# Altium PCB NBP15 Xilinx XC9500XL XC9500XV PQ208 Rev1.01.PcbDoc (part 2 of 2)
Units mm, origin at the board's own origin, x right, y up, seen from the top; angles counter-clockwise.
Board outline 69 x 80.99 mm, 2 copper layers (Top Layer, Bottom Layer); 37 components, 186 nets, 485 pads, 89 vias.
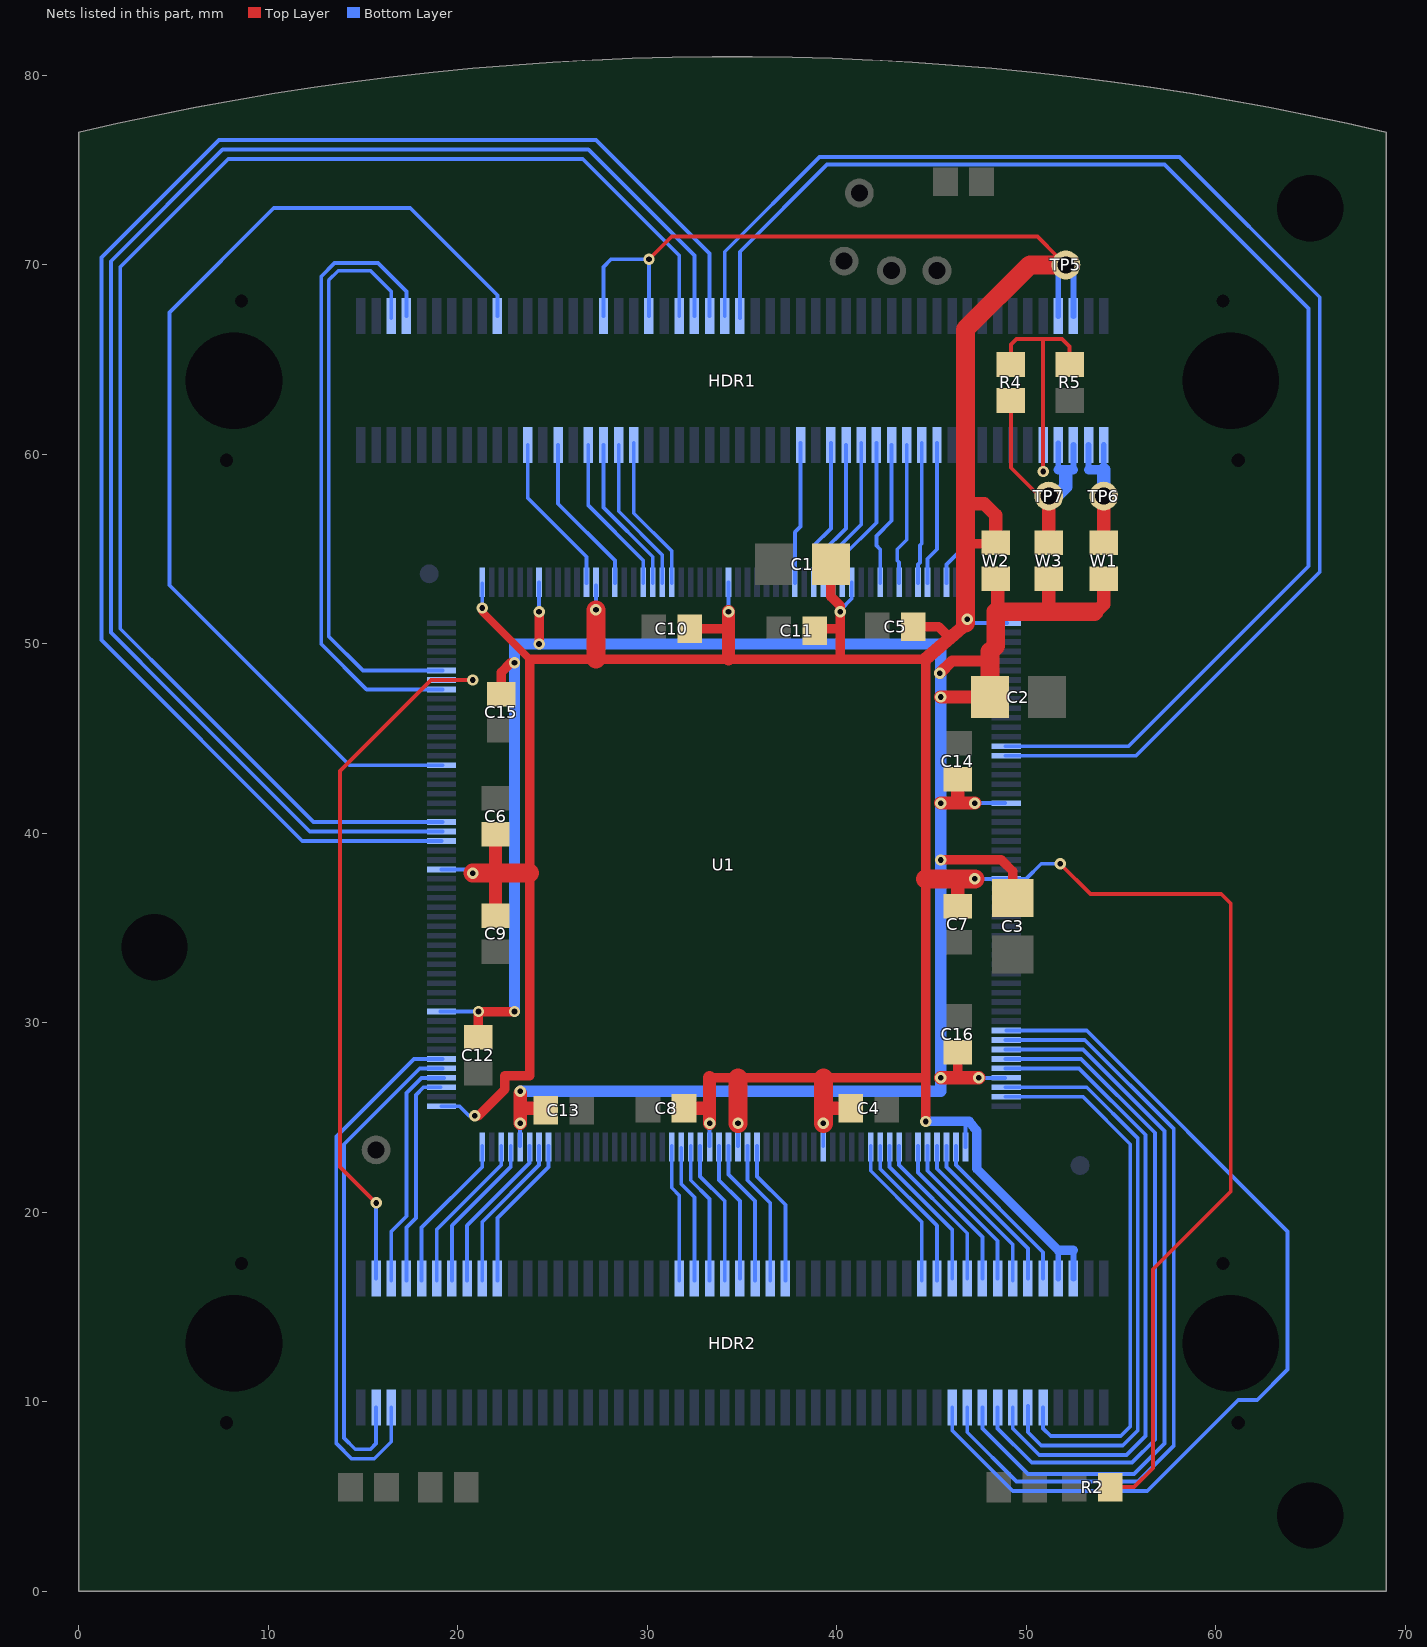
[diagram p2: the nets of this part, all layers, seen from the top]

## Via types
v1: diameter 0.6, hole 0.3, Top Layer to Bottom Layer, tented both sides, 86 vias
v2: diameter 0.9, hole 0.5, Top Layer to Bottom Layer, tented both sides, 3 vias

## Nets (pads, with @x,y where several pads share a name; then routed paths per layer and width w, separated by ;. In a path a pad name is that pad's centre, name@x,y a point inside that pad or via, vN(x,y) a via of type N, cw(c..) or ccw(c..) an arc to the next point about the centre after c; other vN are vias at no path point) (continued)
RAM_ADDR3: HDR1.33 U1.71 | length 8.4
  Bottom Layer w0.2: HDR1.33@27.7,60.5 27.7,57.2 30.3,54.6 U1.71@30.3,53.2
RAM_ADDR4: HDR1.65 U1.89 | length 7.8
  Bottom Layer w0.2: U1.89@39.3,53.2 39.3,54.9 40.5,56.1 HDR1.65@40.5,60.5
RAM_ADDR5: HDR1.69 U1.91 | length 8.1
  Bottom Layer w0.2: U1.91@40.3,53.2 40.3,54.6 42.1,56.4 HDR1.69@42.1,60.6
RAM_ADDR6: HDR1.73 U1.97 | length 7.5
  Bottom Layer w0.2: U1.97@43.3,53.2 43.3,54.3 43.2,54.4 43.2,55 43.7,55.5 HDR1.73@43.7,60.5
RAM_ADDR7: HDR1.77 U1.100 | length 7.6
  Bottom Layer w0.2: U1.100@44.8,53.2 44.8,54.5 45.3,55 HDR1.77@45.3,60.5 HDR1.77@45.3,60.6
RAM_ADDR8: HDR1.75 U1.99 | length 7.5
  Bottom Layer w0.2: U1.99@44.3,53.2 44.3,54.2 44.4,54.3 44.4,55.2 44.5,55.3 HDR1.75@44.5,60.6
RAM_ADDR9: HDR1.71 U1.95 | length 7.7
  Bottom Layer w0.2: U1.95@42.3,53.2 42.3,55 42.1,55.2 42.1,55.7 42.9,56.5 HDR1.71@42.9,60.5
RAM_ADDR10: HDR1.67 U1.90 | length 8
  Bottom Layer w0.2: U1.90@39.8,53.2 39.8,54.8 41.3,56.3 HDR1.67@41.3,60.6
RAM_ADDR11: HDR1.63 U1.88 | length 7.8
  Bottom Layer w0.2: U1.88@38.8,53.2 38.8,55.2 39.7,56.1 HDR1.63@39.7,60.6
RAM_ADDR12: HDR1.59 U1.86 | length 7.5
  Bottom Layer w0.2: U1.86@37.8,53.2 37.8,55.9 38.1,56.2 HDR1.59@38.1,60.5 HDR1.59@38.1,60.6
RAM_ADDR13: HDR1.35 U1.72 | length 8.3
  Bottom Layer w0.2: HDR1.35@28.5,60.5 28.5,57 30.8,54.7 U1.72@30.8,53.2
RAM_ADDR14: HDR1.31 U1.70 | length 8.5
  Bottom Layer w0.2: HDR1.31@26.9,60.5 26.9,57.3 29.8,54.4 U1.70@29.8,53.2
RAM_ADDR15: HDR1.27 U1.67 | length 8.5
  Bottom Layer w0.2: HDR1.27@25.3,60.5 25.3,57.4 28.3,54.4 U1.67@28.3,53.2
RAM_ADDR16: HDR1.23 U1.64 | length 8.6
  Bottom Layer w0.2: HDR1.23@23.7,60.5 23.7,57.7 26.8,54.6 U1.64@26.8,53.2
RAM_CS: HDR1.37 U1.73 | length 8.2
  Bottom Layer w0.2: HDR1.37@29.3,60.6 HDR1.37@29.3,60.5 29.3,56.9 31.3,54.9 U1.73@31.3,53.2
RED0: HDR1.6 U1.47 | length 30.9
  Bottom Layer w0.2: HDR1.6@16.5,67.2 16.5,68.6 15.4,69.7 13.7,69.7 13.2,69.2 13.2,51.2 13.2,50.4 15,48.6 U1.47@19.2,48.6
RED1: HDR1.8 U1.45 | length 33.5
  Bottom Layer w0.2: HDR1.8@17.3,67.3 17.3,68.6 15.8,70.1 13.5,70.1 12.8,69.4 12.8,50 15.2,47.6 U1.45@19.2,47.6
REF_CLK: HDR2.4 U1.46 | length 38.3
  Top Layer w0.2: v1(15.7,20.5) 13.8,22.4 13.8,43.3 18.6,48.1 v1(20.8,48.1)
  Bottom Layer w0.2: HDR2.4@15.7,16.5 v1(15.7,20.5) ; U1.46@19.1,48.1 v1(20.8,48.1)
SCL: HDR2.5 U1.6 | length 28.9
  Bottom Layer w0.2: HDR2.5@16.5,9.7 16.5,7.9 15.6,7 14.4,7 13.6,7.8 13.6,24 17.7,28.1 U1.6@19.2,28.1
SDA: HDR2.3 U1.5 | length 26.3
  Bottom Layer w0.2: HDR2.3@15.7,9.7 15.7,7.8 15.4,7.5 14.6,7.5 14,8.1 14,23.6 18,27.6 U1.5@19.2,27.6
SP0: HDR2.79 U1.148 | length 49.4
  Bottom Layer w0.2: HDR2.79@46.1,9.7 46.1,8.5 49.3,5.3 56.4,5.3 61.2,10.1 62.2,10.1 63.8,11.7 63.8,19 53.2,29.6 U1.148@48.95,29.6
SP1: HDR2.81 U1.149 | length 41.6
  Bottom Layer w0.2: HDR2.81@46.9,9.7 46.9,8.4 49.5,5.8 55.9,5.8 57.8,7.7 57.8,8 57.8,24.4 53.1,29.1 U1.149@48.9,29.1
SP2: HDR2.83 U1.150 | length 39
  Bottom Layer w0.2: HDR2.83@47.7,9.7 47.7,8.6 50.1,6.2 55.7,6.2 57.3,7.8 57.3,24.3 53,28.6 U1.150@48.9,28.6
SP3: HDR2.85 U1.151 | length 36.4
  Bottom Layer w0.2: HDR2.85@48.5,9.7 48.5,8.6 50.3,6.8 55.3,6.8 55.6,6.8 56.8,8 56.8,24.2 52.9,28.1 52.6,28.1 U1.151@48.9,28.1
SP4: HDR2.87 U1.152 | length 33.8
  Bottom Layer w0.2: U1.152@48.9,27.6 52.8,27.6 56.3,24.1 56.3,8.2 55.3,7.2 50.7,7.2 49.3,8.6 HDR2.87@49.3,9.7
SP5: HDR2.89 U1.154 | length 31.3
  Bottom Layer w0.2: U1.154@48.9,26.6 53.2,26.6 55.9,23.9 55.9,8.5 55.1,7.7 50.8,7.7 50.1,8.4 HDR2.89@50.1,9.8
SP6: HDR2.91 U1.155 | length 28.6
  Bottom Layer w0.2: U1.155@48.9,26.1 52.7,26.1 53,26.1 55.5,23.6 55.5,8.7 55,8.2 51.3,8.2 50.9,8.6 HDR2.91@50.9,9.7
SP7: HDR2.92 U1.158 | length 8.9
  Bottom Layer w0.2: U1.158@46.3,23.5 46.3,22.5 50.9,17.9 HDR2.92@50.9,16.5
SP8: HDR2.90 U1.159 | length 8.8
  Bottom Layer w0.2: U1.159@45.8,23.5 45.8,22.4 50.1,18.1 HDR2.90@50.1,16.5
SP9: HDR2.88 U1.160 | length 8.8
  Bottom Layer w0.2: U1.160@45.3,23.5 45.3,22.3 49.3,18.3 HDR2.88@49.3,16.5 HDR2.88@49.3,16.4
SP10: HDR2.86 U1.161 | length 8.5
  Bottom Layer w0.2: U1.161@44.8,23.5 44.8,22.2 48.5,18.5 HDR2.86@48.5,16.5
SP11: HDR2.84 U1.162 | length 8.4
  Bottom Layer w0.2: U1.162@44.3,23.5 44.3,22.1 47.7,18.7 HDR2.84@47.7,16.5
SP12: HDR2.82 U1.164 | length 8.5
  Bottom Layer w0.2: U1.164@43.3,23.5 43.3,22.5 46.9,18.9 HDR2.82@46.9,16.5
SP13: HDR2.80 U1.165 | length 8.4
  Bottom Layer w0.2: U1.165@42.8,23.5 42.8,22.4 46.1,19.1 HDR2.80@46.1,16.5
SP14: HDR2.78 U1.166 | length 8.3
  Bottom Layer w0.2: U1.166@42.3,23.5 42.3,22.3 45.3,19.3 HDR2.78@45.3,16.5 HDR2.78@45.3,16.4
SP15: HDR2.76 U1.167 | length 8.2
  Bottom Layer w0.2: U1.167@41.8,23.5 41.8,22.2 44.5,19.5 HDR2.76@44.5,16.4
SPI_CLK: HDR1.46 U1.30 | length 80.2
  Bottom Layer w0.2: U1.30@19.2,40.1 12.2,40.1 4.9,47.4 1.7,50.6 1.7,57.7 1.7,70.2 7.6,76.1 26.9,76.1 32.5,70.5 HDR1.46@32.5,67.3
SPI_DIN: HDR1.44 U1.31 | length 77.5
  Bottom Layer w0.2: U1.31@19.2,40.6 12.4,40.6 5.4,47.6 2.2,50.8 2.2,58.1 2.2,69.9 7.9,75.6 26.6,75.6 31.7,70.5 HDR1.44@31.7,67.3
SPI_DOUT: HDR1.50 U1.119 | length 75.1
  Bottom Layer w0.2: HDR1.50@34.1,67.3 34.1,70.7 39.1,75.7 58.1,75.7 65.5,68.3 65.5,59.7 65.5,53.8 55.8,44.1 U1.119@48.9,44.1
SPI_MODE: HDR1.52 U1.118 | length 72.1
  Bottom Layer w0.2: HDR1.52@34.9,67.2 34.9,70.5 34.9,70.7 39.5,75.3 57.3,75.3 64.9,67.7 64.9,54.1 55.4,44.6 U1.118@48.9,44.6
SPI_SEL: HDR1.48 U1.29 | length 83
  Bottom Layer w0.2: U1.29@19.15,39.6 11.8,39.6 1.2,50.2 1.2,70.4 7.4,76.6 27.3,76.6 33.3,70.6 HDR1.48@33.3,67.3
SW0: HDR2.44 U1.188 | length 7.3
  Bottom Layer w0.2: U1.188@31.3,23.5 31.3,21.3 31.7,20.9 HDR2.44@31.7,16.4
SW1: HDR2.46 U1.187 | length 7.3
  Bottom Layer w0.2: U1.187@31.8,23.4 31.8,21.5 32.5,20.8 HDR2.46@32.5,16.5 HDR2.46@32.5,16.4
SW2: HDR2.48 U1.186 | length 7.5
  Bottom Layer w0.2: U1.186@32.3,23.5 32.3,21.7 33.3,20.7 HDR2.48@33.3,16.5 HDR2.48@33.3,16.4
SW3: HDR2.50 U1.185 | length 7.6
  Bottom Layer w0.2: U1.185@32.8,23.5 32.8,21.9 34.1,20.6 HDR2.50@34.1,16.4
SW4: HDR2.52 U1.183 | length 7.5
  Bottom Layer w0.2: U1.183@33.8,23.5 33.8,21.7 34.9,20.6 HDR2.52@34.9,16.5
SW5: HDR2.54 U1.182 | length 7.7
  Bottom Layer w0.2: U1.182@34.3,23.5 34.3,22 35.7,20.6 HDR2.54@35.7,16.5 HDR2.54@35.7,16.4
SW6: HDR2.56 U1.180 | length 7.6
  Bottom Layer w0.2: U1.180@35.3,23.5 35.3,21.7 36.5,20.5 HDR2.56@36.5,16.5 HDR2.56@36.5,16.4
SW7: HDR2.58 U1.179 | length 7.7
  Bottom Layer w0.2: U1.179@35.8,23.5 35.8,21.9 37.3,20.4 HDR2.58@37.3,16.5 HDR2.58@37.3,16.4
SWC0: HDR2.18 U1.202 | length 8.3
  Bottom Layer w0.2: HDR2.18@21.3,16.4 21.3,19.5 24.3,22.5 U1.202@24.3,23.5
SWC1: HDR2.16 U1.203 | length 8.5
  Bottom Layer w0.2: HDR2.16@20.5,16.4 HDR2.16@20.5,16.5 20.5,19.3 23.8,22.6 U1.203@23.8,23.5
SWC2: HDR2.14 U1.205 | length 8.4
  Bottom Layer w0.2: HDR2.14@19.7,16.4 19.7,19.3 22.8,22.4 U1.205@22.8,23.5
SWC3: HDR2.6 U1.4 | length 12.6
  Bottom Layer w0.2: HDR2.6@16.5,16.4 16.5,19 17.3,19.8 17.3,26.3 18.1,27.1 U1.4@19.3,27.1
SWR0: HDR2.20 U1.201 | length 8.2
  Bottom Layer w0.2: HDR2.20@22.1,16.4 22.1,19.7 24.8,22.4 U1.201@24.8,23.5
SWR1: HDR2.12 U1.206 | length 8.5
  Bottom Layer w0.2: HDR2.12@18.9,16.4 18.9,19.1 22.3,22.5 U1.206@22.3,23.5
SWR2: HDR2.10 U1.208 | length 8.4
  Bottom Layer w0.2: HDR2.10@18.1,16.4 18.1,19.2 21.3,22.4 U1.208@21.3,23.5
SWR3: HDR2.8 U1.3 | length 11.5
  Bottom Layer w0.2: HDR2.8@17.3,16.4 HDR2.8@17.3,16.5 17.3,19.2 17.8,19.7 17.8,26.2 18.2,26.6 U1.3@19.1,26.6
TEST: HDR1.81 U1.102 | length 7.9
  Bottom Layer w0.2: U1.102@45.8,53.2 45.8,54.2 46.9,55.3 HDR1.81@46.9,60.5 HDR1.81@46.9,60.6
VCC: C1.1 C4.1 C5.1 C6.1 C7.1 C8.1 C9.1 C10.1 C11.1 HDR1.34 HDR1.40 HDR1.94 HDR1.96 HDR2.94 HDR2.96 R2.1 TP5.1 U1.1 U1.26 U1.53 U1.65 U1.79 U1.92 U1.105 U1.132 U1.157 U1.172 U1.181 U1.184 W2.1 | length 278.2
  Top Layer w0.2: v1@21.3,51.7 v1(21.3,51.9) ; v1(30.1,70.3) 31.3,71.5 31.8,71.5 ; 31.4,71.5 50.6,71.5 TP5.1@51.7,70.4 ; v1(51.8,38.4) 53.4,36.8 60.3,36.8 60.8,36.3 60.8,21.1 56.7,17 56.7,6.5 55.7,5.5 R2.1@54.4,5.5 ; R2.1@54.4,5.4 R2.1@54.45,5.4
  Top Layer w0.4: v1@21.3,51.7 23.8,49.2
  Top Layer w0.5: v1(20.9,25.1) 21.1,25.1 22.5,26.5 22.5,27.2 23.8,27.2 23.8,49.2 27.3,49.2 34.3,49.2 40.2,49.2 ; C10.1@32.3,50.8 34.3,50.8 ; 33.3,27.1 44.7,27.1 ; C11.1@38.85,50.8 40.2,50.8 ; C1.1@39.7,54.2 39.7,52.5 40.2,52 40.2,49.2 ; C5.1@44.1,50.9 45.4,50.9 45.988,50.312 ; v1(44.7,24.8) 44.7,27.1 ; 46.8,55.3 W2.1@48.4,55.3 ; 40.2,49.2 44.7,49.2 44.7,37.6 44.7,27.1
  Top Layer w0.7: C9.1@22,35.65 C6.1@22,39.95 ; C8.1@31.95,25.5 33.3,25.5 ; v1(33.3,24.7) 33.3,27.1 ; 34.3,49.2 v1(34.3,51.7) ; 39.3,25.5 C4.1@40.7,25.5 ; 44.7,49.2 45.988,50.312 ; 45.989,50.313 v1@46.843,51.05 ; C7.1@46.4,36.35 46.4,37.6 ; 46.9,65 46.9,57.4 47.8,57.4 48.4,56.8 W2.1@48.4,55.35
  Top Layer w1: v1(20.8,37.9) 23.8,37.9 ; 27.3,49.2 v1(27.3,51.8) ; v1(34.8,24.7) 34.8,27.1 ; v1(39.3,24.7) 39.3,27.1 ; 44.7,37.6 v1(47.3,37.6) ; v1@46.8,51.1 46.8,66.6 50.2,70 TP5.1@52.2,70
  Bottom Layer w0.2: U1.1@19.15,25.6 20.1,25.6 20.6,25.1 v1(20.9,25.1) ; U1.26@19.15,38.1 20.6,38.1 v1(20.8,37.9) ; v1(21.3,51.9) U1.53@21.3,53.2 ; v1(27.3,51.8) U1.65@27.3,53.1 ; HDR1.34@27.7,67.3 27.7,69.9 28.1,70.3 v1(30.1,70.3) HDR1.40@30.1,67.3 ; U1.184@33.3,23.5 v1(33.3,24.7) ; v1(34.3,51.7) U1.79@34.3,53.25 ; U1.181@34.8,23.5 v1(34.8,24.7) ; U1.172@39.3,23.5 v1(39.3,24.7) ; v1(40.2,51.7) 40.2,51.8 40.8,52.4 U1.92@40.8,53.25 ; U1.157@46.8,23.45 46.8,24.7 46.8,24.8 ; v1(46.9,51.3) 47.1,51.1 U1.105@49,51.1 ; v1(47.3,37.6) U1.132@48.95,37.6 ; U1.132@48.9,37.6 50,37.6 50.8,38.4 v1(51.8,38.4)
  Bottom Layer w0.3: HDR2.94@51.7,16.5 51.7,18 ; HDR1.94@51.7,67.3 TP5.1@51.7,70 ; HDR2.96@52.5,16.5 52.5,18 ; HDR1.96@52.5,67.3 TP5.1@52.5,70
  Bottom Layer w0.5: v1(44.7,24.8) 47,24.8 47.4,24.3 47.4,22.3 51.7,18 52.5,18
VCC2V5: HDR1.93 HDR1.95 R4.1 TP7.1 W3.1 | length 14.2
  Top Layer w0.2: R4.1@49.2,62.8 49.2,59.3 TP7.1@51.1,57.4
  Top Layer w0.7: W3.1@51.2,55.3 TP7.1@51.2,57.8
  Bottom Layer w0.3: 51.7,59.2 HDR1.93@51.7,60.6 ; 52.5,59.2 HDR1.95@52.5,60.5
  Bottom Layer w0.5: 51.7,59.2 52.5,59.2
  Bottom Layer w0.7: TP7.1@51.2,57.4 52.1,58.3 52.1,59
VCC5V: HDR1.97 HDR1.99 TP6.1 W1.1 | length 7.8
  Top Layer w0.7: W1.1@54.1,55.3 TP6.1@54.1,57.9
  Bottom Layer w0.3: 53.3,59.2 HDR1.97@53.3,60.5 ; 54.1,59.2 HDR1.99@54.1,60.5
  Bottom Layer w0.5: 53.3,59.2 54.1,59.2
  Bottom Layer w0.7: TP6.1@54.1,57.4 54.1,59.2
VCCINT: C2.1 C3.1 C12.1 C13.1 C14.1 C15.1 C16.1 U1.11 U1.59 U1.124 U1.153 U1.204 W1.2 W2.2 W3.2 | length 138.3
  Top Layer w0.5: C12.1@21.1,29.25 v1(21.1,30.6) v1(23,30.6) ; C15.1@22.3,47.35 22.3,48.5 22.8,49 v1(23,49) ; v1(24.3,50) v1(24.3,51.7) ; v1(45.5,38.6) 48.7,38.6 49.3,38 C3.1@49.3,36.6 ; 46.4,27.1 C16.1@46.4,28.45
  Top Layer w0.6: v1(45.45,48.45) 46.1,49.1 48.1,49.1
  Top Layer w0.7: v1(23.3,24.7) v1@23.3,26.3 ; 23.3,25.5 C13.1@24.9,25.5 ; v1(45.5,27.1) v1(47.5,27.1) ; v1(45.5,41.6) v1(47.3,41.6) ; v1(45.5,47.2) C2.1@48.1,47.2 ; 46.4,41.6 C14.1@46.4,42.85 ; 48.5,50.4 48.5,50.5 ; 48.5,51.7 W2.2@48.5,53.4 ; 51.2,51.7 W3.2@51.2,53.45 ; 53.6,51.6 54.1,52.1 W1.2@54.1,53.5
  Top Layer w1: C2.1@48.1,47.2 48.1,49.6 48.4,49.9 48.4,51.7 ; 48.6,51.7 53.6,51.7
  Bottom Layer w0.2: U1.11@19.1,30.6 U1.11@19.15,30.6 v1(21.1,30.6) ; U1.204@23.3,23.5 v1(23.3,24.7) ; v1(24.3,51.7) U1.59@24.3,53.25 ; v1(47.3,41.6) U1.124@48.9,41.6 ; v1(47.5,27.1) U1.153@48.9,27.1
  Bottom Layer w0.6: v1(23,30.6) 23,50 45.5,50 45.5,26.4 v1(23.3,26.4)
VDRIVE: HDR1.20 U1.37 | length 55.3
  Bottom Layer w0.2: U1.37@19.2,43.6 14.3,43.6 4.8,53.1 4.8,67.5 10.3,73 17.5,73 22.1,68.4 HDR1.20@22.1,67.3
VREF: HDR1.91 R4.2 R5.1 | length 14
  Top Layer w0.2: R4.2@49.2,64.7 49.2,65.8 49.5,66.1 51.9,66.1 52.3,65.7 R5.1@52.3,64.6 ; v1(50.9,59.1) 50.9,66.1
  Bottom Layer w0.2: v1(50.9,59.1) HDR1.91@50.9,60.5
pads on no net: HDR1.MH1 HDR1.MH2 HDR1.MH3 HDR1.MH4 HDR1.MH5 HDR1.MH6 HDR2.93 HDR2.95 HDR2.97 HDR2.99 HDR2.MH1 HDR2.MH2 HDR2.MH3 HDR2.MH4 HDR2.MH5 HDR2.MH6 U1.16 U1.25 U1.28

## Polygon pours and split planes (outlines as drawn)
GND on Top Layer "Top Layer-GND" (solid, remove dead copper, pour order 1000): 0.45,-0.295 69.45,-0.295 69.45,81.005 0.55,81.005 0.55,-0.195

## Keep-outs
Bottom Layer:
  circle w0.2: c18.5,53.7 r2
  circle w0.2: c52.85,22.475 r2
Keep-Out Layer:
  lines w1.8: 68.999,77 ccw(c34.5,-69.801) 0.001,77 0,0 69,0 ; 69.1,0 69.1,77

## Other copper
Top Layer:
  rectangle net VCC: 23.5,26.9 44.8,49.1
Bottom Layer:
  rectangle net VCC: 51.6,68.6 52.6,70.6
  rectangle net GND: 22,27.3 24.1,29.9
  rectangle net GND: 23.9,27.3 44.5,49.1

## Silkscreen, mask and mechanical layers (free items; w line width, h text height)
Top Overlay:
  lines w0.254: 38.4,68.1 40.4,70.1 ; 39.6,66.4 42.9,69.7 ; 39.9,75.1 41.2,73.8 ; 45.2,69.6 45.3,69.7 46.6,68.4 ; 51.2,57.6 54.1,60.5 ; 52.1,70 53.6,71.5 ; 54.1,57.7 55.2,58.8 ; 51.2,57.4 51.2,57.4
  text "(TDO)" at 36.2,74.8 h0.8
  text "(+3V3)" at 56.3,71 h0.8
  text "(TDI)" at 49.3,67.9 h0.8
  text "(TMS)" at 34.7,67.7 h0.8
  text "(TCK)" at 35.9,66 h0.8
  text "(+2V5)" at 54.4,59.7 h0.8
  text "(+5V)" at 57.9,58.4 h0.8
  text "(FPGA CLK)" at 19.8,22.8 h0.8
  text "LOADED" at 17.3,2.8 h0.8
  text "POWER" at 47.6,2.7 h0.8
Bottom Overlay:
  drawing of 849 lines, arcs and shapes, not listed
  text "REV 1.01" at 47.7,76.5 h1.3
  text "NBP15" at 54.9,76.5 h1.3
PCB Boundary:
  the board outline again, w0.25
  text "PCB boundary coincides with centre-line of tracks and arc" at 0,-12 h0.75
Gerber ID:
  text ".Layer_Name" at 0,-6 h0.75
Printout ID:
  text ".Printout_Name" at 0,-10 h0.75
Design Information:
  drawing of 719 lines, arcs and shapes, not listed
  text "NBP15 REV 1.01" at 317.627,202.041 h1.27
  text "DESIGN INFORMATION" at 261.62,201.914 h1.52
  text "BOARD NAME:" at 299.212,201.914 h1.52
  text "BOARD TECHNOLOGY" at 261.62,199.374 h1.52
  text "BOARD SIZE (REFER ALSO PROFILING INFORMATION)" at 309.88,199.374 h1.27
  text "69.00mm" at 312.6,197.1 h1.52
  text "11.811" at 277.419,197.012 h1.52
  text "81.00mm" at 335.6,197 h1.52
  text "7.874" at 291.389,196.885 h1.52
  text "7.874" at 264.446,196.834 h1.52
  text "X" at 328.549,196.326 h1.78
  text "(MIN. TRACK/   PADS  /   CLEARANCE     IN 0.001'')" at 260.096,194.294 h1.27
  text "MINIMUM ANNULAR RING 0.05MM (0.002'') EXTERNAL PER IPC-2221 CLASS 3 LEVEL C AND IS THE" at 261.62,191.754 h1.27
  text "MANUFACTURING REGISTRATION ALLOWANCE" at 261.62,189.468 h1.27
  text "LAND SIZE CALCULATION MINIMUM - NOMINAL HOLE SIZE + 0.508MM (0.020'')" at 261.62,186.674 h1.27
  text "AS INSTRUCTED" at 347.65,182.28 h1.52
  text "X" at 299.263,182.153 h1.52
  text "CIRCUIT TYPE:" at 261.62,182.102 h1.52
  text "SS" at 284.48,182.102 h1.27
  text "DS" at 302.26,182.102 h1.27
  text "X" at 316.865,182.102 h1.52
  text "PTH" at 320.04,182.102 h1.27
  text "ML" at 330.962,182.102 h1.27
  text "No. OFF" at 337.82,182.102 h1.27
  text "FINGER CONNECTOR DIM PER:" at 261.62,179.054 h1.52
  text "AS SHOWN" at 337.82,179.054 h1.27
  text "No. OFF TOTAL" at 278.384,176.26 h1.52
  text "ONE SIDE" at 320.04,176.26 h1.27
  text "BOTH SIDES" at 337.82,176.006 h1.27
  text "VIAS:" at 261.62,173.339 h1.52
  text "NONE" at 273.05,173.339 h1.14
  text "X" at 281.432,173.339 h1.52
  text "FEED THRU'" at 284.48,173.339 h1.14
  text "X" at 299.212,173.339 h1.52
  text "TENTED" at 302.26,173.339 h1.14
  text "BURIED LAYER SEQUENCE" at 320.04,173.339 h1.14
  text "UNIQUE DRILL" at 284.48,170.291 h1.14
  text "2 SIZE" at 302.26,170.291 h1.14
  text "BLIND LAYER SEQUENCE" at 320.04,170.291 h1.14
  text "Layer Stack Manager (Protel)" at 297.053,168.005 h1.27
  text "X" at 334.772,168.005 h1.52
  text "AS SHOWN" at 337.82,168.005 h1.27
  text "LAYER CONSTRUCTION PER:" at 261.62,167.878 h1.52
  text "Protel" at 342.646,165.338 h1.27
  text "(PFW)" at 352.933,165.211 h1.27
  text "ARTWORK:" at 261.62,165.084 h1.52
  text "MANUAL" at 284.48,165.084 h1.27
  text "DIGITISED" at 302.26,165.084 h1.27
  text "X" at 316.992,165.084 h1.52
  text "CAD" at 320.04,165.084 h1.27
  text "TYPE" at 330.962,165.084 h1.27
  text "ARTWORK/PATTERN MASTER LIST" at 261.62,160.385 h1.52
  text "DESCRIPTION" at 262.89,157.972 h1.27
  text "DRAWING No./CAD FILE REF." at 281.559,157.972 h1.27
  text "LAYER NAME" at 322.834,157.972 h1.27
  text "GERBER FILE REF" at 343.586,157.896 h1.27
  text "PCB FILE" at 261.366,155.432 h1.27
  text "BOC_XC95288_PQ208" at 281.237,155.356 h1.27
  text "PcbDoc" at 312.979,155.356 h1.02
  text "Top Paste Mask" at 321.158,152.892 h1.02
  text "GTP" at 363.779,152.816 h1.27
  text "GERBER FILE" at 261.366,152.765 h1.27
  text "GTO" at 363.728,150.327 h1.27
  text "Top Overlay" at 321.158,150.301 h1.02
  text "GERBER FILE" at 261.366,150.225 h1.27
  text "Top Solder Mask" at 321.158,147.863 h1.02
  text "GTS" at 363.779,147.736 h1.27
  text "GERBER FILE" at 261.366,147.685 h1.27
  text "TOP LAYER" at 321.158,145.272 h1.02
  text "GTL" at 363.779,145.196 h1.27
  text "GERBER FILE" at 261.366,145.145 h1.27
  text "BOTTOMLAYER" at 321.158,142.732 h1.02
  text "GBL" at 363.779,142.656 h1.27
  text "GERBER FILE" at 261.366,142.605 h1.27
  text "Bottom Solder Mask" at 321.158,140.243 h1.02
  text "GBS" at 363.779,140.116 h1.27
  text "GERBER FILE" at 261.366,140.065 h1.27
  text "Bottom Overlay" at 321.158,137.652 h1.02
  text "GBO" at 363.779,137.576 h1.27
  text "GERBER FILE" at 261.366,137.525 h1.27
  text "Bottom Paste Mask" at 321.158,135.163 h1.02
  text "GBP" at 363.779,135.036 h1.27
  text "GERBER FILE" at 261.366,134.985 h1.27
  text "PCB Boundary" at 321.158,132.572 h1.02
  text "GM1" at 363.779,132.496 h1.27
  text "GERBER FILE" at 261.366,132.445 h1.27
  text "APERTURE LIST" at 261.366,130.032 h1.27
  text "APR" at 313.979,129.956 h1.27
  text "DRILL REPORT" at 261.366,127.492 h1.27
  text "DRR" at 313.979,127.416 h1.27
  text "EXCELLON DRILL" at 261.366,124.952 h1.27
  text "TXT" at 313.979,124.876 h1.27
  text "MATERIAL:" at 261.62,99.298 h1.52
  text "GLASS FIBRE EPOXY RESIN NEMA GRADE FR4 (MIL-S-13949H)" at 287.274,99.044 h1.27
  text "X" at 284.607,98.917 h1.52
  text "THICKNESS:" at 269.494,96.123 h1.27
  text "0.8mm" at 287.274,96.123 h1.27
  text "1.2mm" at 304.927,96.123 h1.27
  text "1.6mm" at 322.58,96.123 h1.27
  text "2.4mm" at 340.36,96.123 h1.27
  text "3.2mm" at 358.14,96.123 h1.27
  text "X" at 320.167,95.996 h1.52
  text "TOLERANCE:" at 269.367,93.075 h1.27
  text "IN A/W IPC-D-300G CLASS" at 287.02,93.075 h1.27
  text "3 LEVEL B" at 321.945,93.075 h1.27
  text "OTHER +/-" at 340.36,93.075 h1.27
  text "X" at 284.607,92.948 h1.52
  text "BOW & TWIST:" at 266.954,90.027 h1.27
  text "IN A/W IPC-D-300G CLASS" at 287.02,90.027 h1.27
  text "3 LEVEL B" at 321.945,90.027 h1.27
  text "AS SHOWN" at 340.487,89.9 h1.27
  text "X" at 284.607,89.773 h1.52
  text "COPPER THICKNESS (FINISHED)" at 269.367,86.725 h1.27
  text "OUTER:" at 274.193,84.439 h1.27
  text "18um" at 287.274,84.439 h1.27
  text "35um" at 314.325,84.439 h1.27
  text "70um" at 340.614,84.439 h1.27
  text "X" at 311.582,84.236 h1.52
  text "INNER SIGNAL:" at 265.811,81.391 h1.27
  text "18um" at 287.274,81.391 h1.27
  text "35um" at 314.325,81.391 h1.27
  text "70um" at 340.614,81.391 h1.27
  text "INNER PWR:" at 269.494,78.343 h1.27
  text "18um" at 287.274,78.343 h1.27
  text "35um" at 314.325,78.343 h1.27
  text "70um" at 340.614,78.343 h1.27
  text "STRUCTURE:" at 261.62,75.295 h1.52
  text "REFER" at 287.274,75.295 h1.27
  text "AS PER DRAWING No." at 287.147,72.12 h1.27
  text "AS SHOWN" at 340.487,72.12 h1.27
  text "X" at 337.947,71.993 h1.52
  text "DRILLING:" at 261.62,69.326 h1.52
  text "VIEWED FROM:" at 266.573,67.04 h1.27
  text "COMPONENT SIDE" at 287.274,67.04 h1.14
  text "SOLDER SIDE" at 314.071,67.04 h1.14
  text "X" at 284.607,66.786 h1.52
  text "REFERENCE:" at 268.859,63.992 h1.27
  text "AS SHOWN" at 287.147,63.865 h1.14
  text "PATTERN MASTER LIST" at 314.198,63.865 h1.14
  text "X" at 337.947,63.865 h1.52
  text "NC_DRILL FILES" at 340.487,63.865 h1.14
  text "X" at 284.607,63.738 h1.52
  text "PTH MINIMUM COPPER THICKNESS:" at 274.701,60.944 h1.27
  text "20um" at 314.325,60.944 h1.27
  text "X" at 311.658,60.817 h1.52
  text "OTHER" at 340.487,60.817 h1.27
  text "NPTH:" at 275.209,57.896 h1.27
  text "TENTED" at 287.147,57.769 h1.14
  text "X" at 311.658,57.769 h1.52
  text "PADS REMOVED" at 314.198,57.769 h1.14
  text "REMOVE PADS" at 340.487,57.769 h1.14
  text "X" at 284.607,57.642 h1.52
  text "2nd DRILL" at 287.147,54.721 h1.14
  text "BOTH" at 314.198,54.721 h1.14
  text "AS SHOWN" at 326.517,54.721 h1.14
  text "NONE" at 340.487,54.721 h1.14
  text "BOARD FINISH:" at 261.62,51.8 h1.52
  text "X" at 284.607,51.673 h1.52
  text "ETCHING" at 287.147,51.673 h1.14
  text "REFER PATTERN MASTER LIST" at 314.198,51.673 h1.14
  text "LEGEND / SCREEN PRINT:" at 281.94,48.752 h1.27
  text "NONE" at 314.198,48.625 h1.14
  text "COMPONENT" at 326.517,48.625 h1.14
  text "SOLDER" at 340.487,48.625 h1.14
  text "X" at 323.977,48.498 h1.52
  text "X" at 337.947,48.498 h1.52
  text "COLOUR:" at 272.161,45.704 h1.27
  text "WHITE" at 287.147,45.577 h1.14
  text "YELLOW" at 314.198,45.577 h1.14
  text "OTHER" at 340.487,45.577 h1.14
  text "X" at 284.607,45.45 h1.52
  text "X" at 284.607,42.529 h1.52
  text "LIQUID PHOTOIMAGEABLE" at 287.147,42.529 h1.14
  text "SCREEN PRINT" at 326.517,42.529 h1.14
  text "MATTE" at 287.147,39.481 h1.14
  text "GLOSS" at 299.847,39.481 h1.14
  text "GREEN" at 314.198,39.481 h1.14
  text "BLUE" at 326.517,39.481 h1.14
  text "G/Y" at 340.487,39.481 h1.14
  text "OTHER" at 351.917,39.481 h1.14
  text "X" at 297.18,39.354 h1.52
  text "SOLDER MASK COLOUR:" at 261.62,36.56 h1.14
  text "BLACK" at 287.147,36.433 h1.14
  text "GREEN" at 299.847,36.433 h1.14
  text "YELLOW" at 314.198,36.433 h1.14
  text "BLUE" at 326.517,36.433 h1.14
  text "OTHER" at 340.487,36.433 h1.14
  text "X" at 284.48,36.306 h1.52
  text "TRACK FINISH:" at 261.62,33.512 h1.52
  text "SELECTIVE SOLDER (HASL)" at 287.147,33.385 h1.14
  text "REFLOW SOLDER" at 326.517,33.385 h1.14
  text "SELECTIVE GOLD" at 287.147,30.337 h1.14
  text "um  (AREA" at 314.198,30.337 h1.14
  text "sq. mm)" at 342.011,30.337 h1.14
  text "X" at 284.607,27.289 h1.52
  text "IMMERSION GOLD" at 287.147,27.289 h1.14
  text "OTHER" at 326.517,27.289 h1.14
  text "EDGE BOARD" at 261.62,24.368 h1.52
  text "1.3um HARD GOLD OVER 5um     NICKEL / TIN-NICKEL" at 287.147,24.241 h1.14
  text "CONTACTS:" at 261.62,22.209 h1.52
  text "HARD FINISH GOLDE PLATE" at 287.147,21.193 h1.14
  text "OTHER" at 326.517,21.193 h1.14
  text "AS SHOWN" at 287.147,18.145 h1.14
  text "REFER" at 326.517,18.145 h1.14
  text "PROFILING:" at 261.62,15.097 h1.52
  text "AS DIMENSIONED, MEASURED AND CUT FROM SPECIFIED DATUM." at 287.147,15.097 h1.14
  text "X" at 284.607,14.97 h1.52
  text "REFER PCB BLANK DWG No." at 287.274,12.176 h1.27
  text "USE PROFILE / ROUTE TAPE SUPPLIED (REFER PATTERN MASTER LIST)" at 287.274,9.128 h1.27
  text "SQUARE CUT" at 287.274,6.08 h1.27
  text "N.C. ROUTE" at 305.054,6.08 h1.27
  text "V. SCORE" at 322.834,6.08 h1.27
  text "BLANK" at 340.614,6.08 h1.27
  text "ACCEPTABILITY:" at 261.62,3.413 h1.52
  text "MATERIALS AND WORKMANSHIP FOR ALL PRINTED WIRING BOARDS TO MEET" at 283.845,3.286 h1.27
  text "OR EXCEED THE REQUIREMENTS OF:" at 283.845,0.492 h1.27
  text "IPC-6011/12 AND IPC-A-600E" at 287.401,-2.175 h1.27
  text "1" at 322.961,-2.175 h1.27
  text "2" at 331.851,-2.175 h1.27
  text "X" at 329.184,-2.302 h1.52
  text "X" at 284.734,-2.429 h1.52
  text "3" at 340.741,-4.334 h1.27
  text "UL CERTIFICATION" at 287.401,-5.223 h1.27
  text "AUSTEL" at 322.961,-5.223 h1.27
  text "X" at 284.734,-5.35 h1.52
  text "ML-P-55110F GRP" at 286.893,-8.271 h1.02
  text "A" at 305.181,-8.271 h1.27
  text "B" at 314.071,-8.271 h1.27
  text "AS2546" at 322.961,-8.271 h1.27
  text "OTHER" at 340.741,-8.271 h1.27
  text "ADDITIONAL" at 261.62,-11.192 h1.52
  text "NONE" at 287.401,-11.446 h1.27
  text "SAMPLE PLAN" at 305.181,-11.446 h1.27
  text "MIL-P-55110E SERIAL Nos. PER ORDER" at 322.961,-11.446 h1.27
  text "REQUIREMENTS:" at 261.62,-13.605 h1.52
  text "NONE" at 287.401,-14.494 h1.27
  text "ML-P-55110F GRP" at 304.673,-14.494 h1.02
  text "A" at 322.961,-14.494 h1.27
  text "B" at 331.851,-14.494 h1.27
  text "IPC CLASS:" at 337.82,-14.494 h1.27
  text "1" at 353.314,-14.494 h1.27
  text "2" at 359.664,-14.494 h1.27
  text "3" at 366.014,-14.494 h1.27
  text "QUALITY RELEASE REPORT" at 305.181,-17.542 h1.27
  text "OTHER" at 345.694,-17.542 h1.27
  text "PER ORDER" at 354.203,-17.669 h1.27
  text "X" at 343.027,-17.796 h1.52
  text "NONE" at 305.181,-20.59 h1.27
  text "REQUIRED" at 322.961,-20.59 h1.27
  text "PER ORDER" at 345.821,-20.59 h1.27
  text "ELECTRICAL TEST:" at 261.62,-20.717 h1.52
  text "X" at 320.294,-20.717 h1.52
  text "NONE" at 305.181,-23.638 h1.27
  text "1 SIDE" at 322.834,-23.638 h1.14
  text "2 SIDES" at 334.01,-23.638 h1.14
  text "MIN. PITCH" at 345.694,-23.638 h1.27
  text "0.65mm" at 359.283,-23.638 h1.27
  text "SURFACE MOUNT:" at 261.62,-23.765 h1.52
  text "X" at 331.775,-23.841 h1.52
  text "NONE" at 305.181,-26.686 h1.27
  text "FOIL" at 322.961,-26.686 h1.27
  text "LEGEND" at 334.391,-26.686 h1.27
  text "REFER" at 345.694,-26.686 h1.27
  text "MANUFACTURER'S ID/LOGO:" at 261.62,-26.813 h1.52
  text "ISO9001/AS3901" at 308.991,-29.734 h1.27
  text "NONE" at 345.694,-29.734 h1.27
  text "MANUFACTURER'S ACCREDITATION:" at 261.62,-29.861 h1.52
  text "X" at 306.324,-29.861 h1.52
  text "PER ORDER" at 305.181,-32.782 h1.27
  text "REFER" at 322.961,-32.782 h1.27
  text "PACKAGING AND HANDLING:" at 261.62,-32.909 h1.52
  text "X" at 302.514,-33.036 h1.52
Sheet:
  drawing of 1882 lines, arcs and shapes, not listed
  text "1" at 3.717,207.391 h1.78
  text "2" at 52.756,207.391 h1.78
  text "3" at 102.015,207.391 h1.78
  text "4" at 151.308,207.391 h1.78
  text "5" at 200.584,207.391 h1.78
  text "6" at 249.606,207.391 h1.78
  text "7" at 299.136,207.391 h1.78
  text "8" at 348.158,207.391 h1.78
  text "A" at -18.415,173.406 h1.78
  text "A" at 370.205,173.406 h1.78
  text "B" at -18.415,102.794 h1.78
  text "B" at 370.205,102.794 h1.78
  text "C" at -18.415,32.182 h1.78
  text "C" at 370.205,32.182 h1.78
  text "D" at -18.415,-37.922 h1.78
  text "D" at 370.205,-37.922 h1.78
  text "ENGINEER:" at 255.27,-38.1 h1.14
  text "TITLE:" at 293.37,-38.1 h1.14
  text "PCB DESIGNER:" at 255.27,-45.593 h1.14
  text "DATE:" at 255.27,-53.34 h1.14
  text "PART NO.:" at 293.37,-53.34 h1.14
  text "REV:" at 346.71,-53.34 h1.14
  text "Altium Limited" at 222.25,-55.88 h1.78
  text ".PRINT_DATE" at 256.54,-56.388 h1.78
  text "12a Rodborough Rd" at 222.25,-58.42 h1.78
  text "Frenchs Forest" at 222.25,-60.96 h1.78
  text "FILE NAME:" at 255.27,-60.96 h1.14
  text "DWG NO:" at 293.37,-60.96 h1.14
  text "SCALE:" at 346.71,-60.96 h1.14
  text "NSW 2086" at 222.25,-63.5 h1.78
  text ".PCB_FILE_NAME_NO_PATH" at 256.54,-64.008 h1.78
  text "1" at 3.717,-69.469 h1.78
  text "2" at 52.756,-69.469 h1.78
  text "3" at 102.015,-69.469 h1.78
  text "4" at 151.308,-69.469 h1.78
  text "5" at 200.584,-69.469 h1.78
  text "6" at 249.606,-69.469 h1.78
  text "7" at 299.136,-69.469 h1.78
  text "8" at 348.158,-69.469 h1.78
Drill Drawing:
  text ".Legend" at 0,-8 h0.75

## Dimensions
0,0 to 69,0 on Dimensions
0,0 to 0.001,77 on Dimensions
34.5,-69.801 to 34.5,84 on Dimensions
